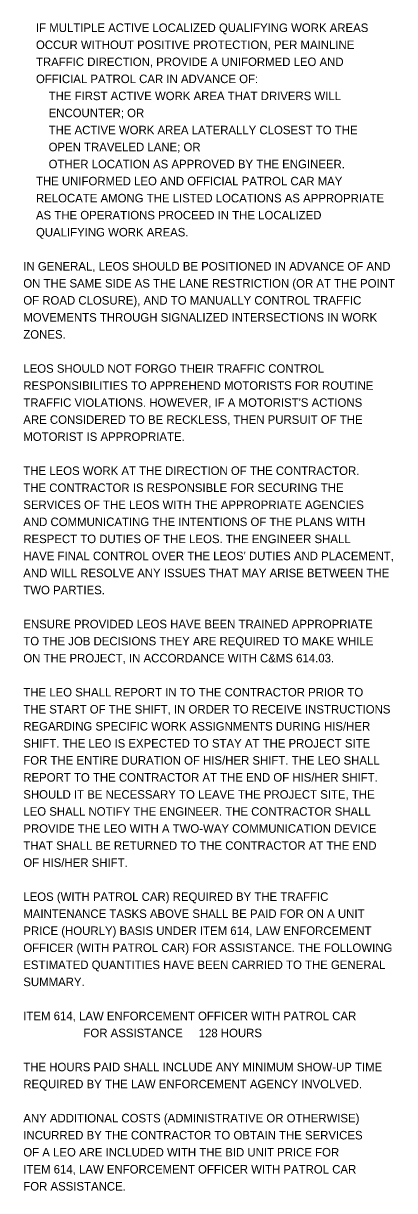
# Model space of a CAD drawing. Extents: x -9 to 65.1, y -15.6 to 23.2.
# Drawn here: x 58.98 to 65.09, y -15.61 to 3.57 of the extents above; entities that cross this region are included whole.
import ezdxf

# ---------------------------------------------------------------- set-up
doc = ezdxf.new("R2010")
doc.units = 0
doc.layers.add('SH_Text', color=7, linetype='Continuous')

msp = doc.modelspace()

# ---------------------------------------------------------------- texts
at = {"layer": 'SH_Text'}
for s, p in [('    IF MULTIPLE ACTIVE LOCALIZED QUALIFYING WORK AREAS', (58.983, 3.43)), ('    OCCUR WITHOUT POSITIVE PROTECTION, PER MAINLINE', (58.983, 3.15)), ('    TRAFFIC DIRECTION, PROVIDE A UNIFORMED LEO AND', (58.983, 2.87)), ('    OFFICIAL PATROL CAR IN ADVANCE OF:', (58.983, 2.59)), ('        THE FIRST ACTIVE WORK AREA THAT DRIVERS WILL', (58.983, 2.31)), ('        ENCOUNTER; OR', (58.983, 2.03)), ('        THE ACTIVE WORK AREA LATERALLY CLOSEST TO THE', (58.983, 1.75)), ('        OPEN TRAVELED LANE; OR', (58.983, 1.47)), ('        OTHER LOCATION AS APPROVED BY THE ENGINEER.', (58.983, 1.19)), ('    THE UNIFORMED LEO AND OFFICIAL PATROL CAR MAY', (58.983, 0.91)), ('    RELOCATE AMONG THE LISTED LOCATIONS AS APPROPRIATE', (58.983, 0.63)), ('    AS THE OPERATIONS PROCEED IN THE LOCALIZED', (58.983, 0.35)), ('    QUALIFYING WORK AREAS.', (58.983, 0.07)), ('IN GENERAL, LEOS SHOULD BE POSITIONED IN ADVANCE OF AND', (58.983, -0.49)), ('ON THE SAME SIDE AS THE LANE RESTRICTION (OR AT THE POINT', (58.983, -0.77)), ('OF ROAD CLOSURE), AND TO MANUALLY CONTROL TRAFFIC', (58.983, -1.05)), ('MOVEMENTS THROUGH SIGNALIZED INTERSECTIONS IN WORK', (58.983, -1.33)), ('ZONES.', (58.983, -1.61)), ('LEOS SHOULD NOT FORGO THEIR TRAFFIC CONTROL', (58.983, -2.17)), ('RESPONSIBILITIES TO APPREHEND MOTORISTS FOR ROUTINE', (58.983, -2.45)), ("TRAFFIC VIOLATIONS. HOWEVER, IF A MOTORIST'S ACTIONS", (58.983, -2.73)), ('ARE CONSIDERED TO BE RECKLESS, THEN PURSUIT OF THE', (58.983, -3.01)), ('MOTORIST IS APPROPRIATE.', (58.983, -3.29)), ('THE LEOS WORK AT THE DIRECTION OF THE CONTRACTOR.', (58.983, -3.85)), ('THE CONTRACTOR IS RESPONSIBLE FOR SECURING THE', (58.983, -4.13)), ('SERVICES OF THE LEOS WITH THE APPROPRIATE AGENCIES', (58.983, -4.41)), ('AND COMMUNICATING THE INTENTIONS OF THE PLANS WITH', (58.983, -4.69)), ('RESPECT TO DUTIES OF THE LEOS. THE ENGINEER SHALL', (58.983, -4.97)), ("HAVE FINAL CONTROL OVER THE LEOS' DUTIES AND PLACEMENT,", (58.983, -5.25)), ('AND WILL RESOLVE ANY ISSUES THAT MAY ARISE BETWEEN THE', (58.983, -5.53)), ('TWO PARTIES.', (58.983, -5.81)), ('ENSURE PROVIDED LEOS HAVE BEEN TRAINED APPROPRIATE', (58.983, -6.37)), ('TO THE JOB DECISIONS THEY ARE REQUIRED TO MAKE WHILE', (58.983, -6.65)), ('ON THE PROJECT, IN ACCORDANCE WITH C&MS 614.03.', (58.983, -6.93)), ('THE LEO SHALL REPORT IN TO THE CONTRACTOR PRIOR TO', (58.983, -7.49)), ('THE START OF THE SHIFT, IN ORDER TO RECEIVE INSTRUCTIONS', (58.983, -7.77)), ('REGARDING SPECIFIC WORK ASSIGNMENTS DURING HIS/HER', (58.983, -8.05)), ('SHIFT. THE LEO IS EXPECTED TO STAY AT THE PROJECT SITE', (58.983, -8.33)), ('FOR THE ENTIRE DURATION OF HIS/HER SHIFT. THE LEO SHALL', (58.983, -8.61)), ('REPORT TO THE CONTRACTOR AT THE END OF HIS/HER SHIFT.', (58.983, -8.89)), ('SHOULD IT BE NECESSARY TO LEAVE THE PROJECT SITE, THE', (58.983, -9.17)), ('LEO SHALL NOTIFY THE ENGINEER. THE CONTRACTOR SHALL', (58.983, -9.45)), ('PROVIDE THE LEO WITH A TWO-WAY COMMUNICATION DEVICE', (58.983, -9.73)), ('THAT SHALL BE RETURNED TO THE CONTRACTOR AT THE END', (58.983, -10.01)), ('OF HIS/HER SHIFT.', (58.983, -10.29)), ('LEOS (WITH PATROL CAR) REQUIRED BY THE TRAFFIC', (58.983, -10.85)), ('MAINTENANCE TASKS ABOVE SHALL BE PAID FOR ON A UNIT', (58.983, -11.13)), ('PRICE (HOURLY) BASIS UNDER ITEM 614, LAW ENFORCEMENT', (58.983, -11.41)), ('OFFICER (WITH PATROL CAR) FOR ASSISTANCE. THE FOLLOWING', (58.983, -11.69)), ('ESTIMATED QUANTITIES HAVE BEEN CARRIED TO THE GENERAL', (58.983, -11.97)), ('SUMMARY.', (58.983, -12.25)), ('ITEM 614, LAW ENFORCEMENT OFFICER WITH PATROL CAR', (58.983, -12.81)), ('                   FOR ASSISTANCE     128 HOURS', (58.983, -13.09)), ('THE HOURS PAID SHALL INCLUDE ANY MINIMUM SHOW-UP TIME', (58.983, -13.65)), ('REQUIRED BY THE LAW ENFORCEMENT AGENCY INVOLVED.', (58.983, -13.93)), ('ANY ADDITIONAL COSTS (ADMINISTRATIVE OR OTHERWISE)', (58.983, -14.49)), ('INCURRED BY THE CONTRACTOR TO OBTAIN THE SERVICES', (58.983, -14.77)), ('OF A LEO ARE INCLUDED WITH THE BID UNIT PRICE FOR', (58.983, -15.05)), ('ITEM 614, LAW ENFORCEMENT OFFICER WITH PATROL CAR', (58.983, -15.33)), ('FOR ASSISTANCE.', (58.983, -15.61))]:
    msp.add_text(s, height=0.14, dxfattribs=at).set_placement(p)

doc.saveas('drawing.dxf')
